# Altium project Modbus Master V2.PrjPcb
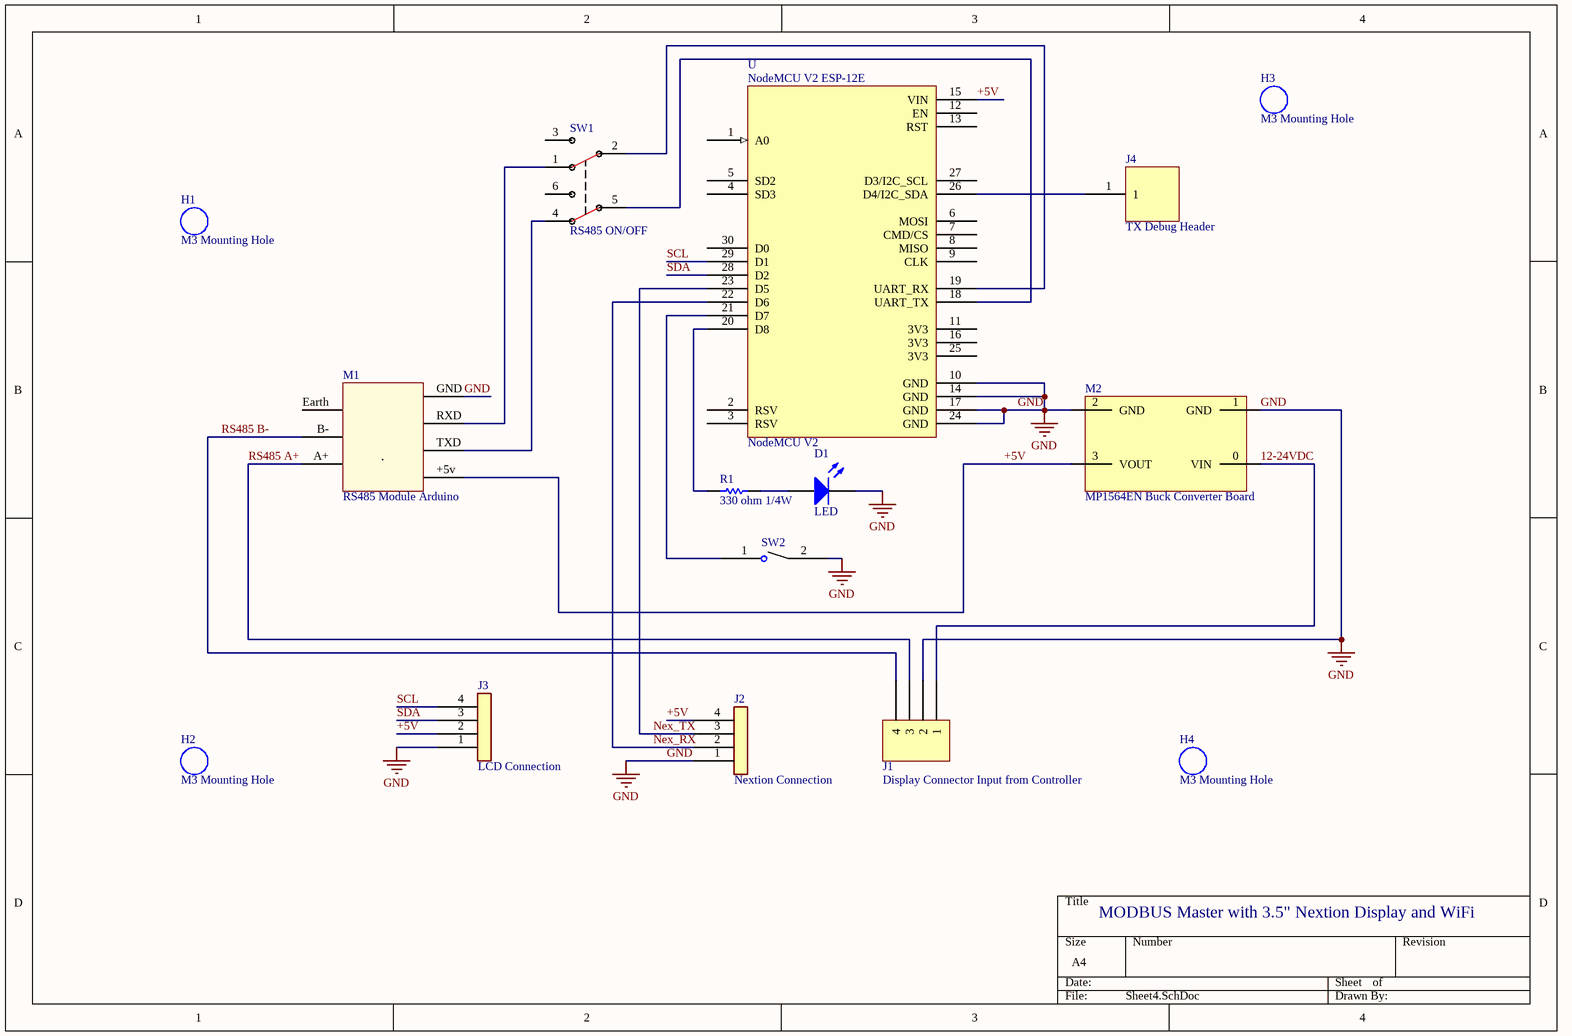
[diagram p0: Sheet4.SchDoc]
1 sheet, 15 parts. Net scope: global (net labels, ports and power ports of the same name join across sheets).

## Sheet Sheet4.SchDoc
size A4

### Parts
D1  LED  [PCB-6hmn14p3euwrtpae4j9f-1]
H1  M3 Mounting Hole  [PCB-sb9r54v1ukudlsmquqqd-1]
H2  M3 Mounting Hole  [PCB-sb9r54v1ukudlsmquqqd-1]
H3  M3 Mounting Hole  [PCB-sb9r54v1ukudlsmquqqd-1]
H4  M3 Mounting Hole  [PCB-sb9r54v1ukudlsmquqqd-1]
J1  Display Connector Input from Controller  [PCB-7alpfj4z7cactpb4urhw-1]
J2  Nextion Connection  [PCB-tykp9fg8zejphh3ras5e-1]
J3  LCD Connection  [PCB-tykp9fg8zejphh3ras5e-1]
J4  TX Debug Header  [PCB-jazjlqhe2dz3b1rp09od-1]
M1  RS485 Module Arduino  [PCB-fd05ettsbss648nlesx9-1]
M2  MP1564EN Buck Converter Board  [PCB-li055xbo9p6zs65dyiu8-1]
R1  330 ohm 1/4W  [PCB-b0svi7yxgb64se8nuirk-1]
SW1  RS485 ON/OFF  [PCB-4o0hqz6pdnge3ng8ta2d-1]
SW2  TE Connectivity 1825910-7  [PCB-6xsl2ocvzxedp18o12ji-1]  (value not drawn)
U  NodeMCU V2  [PCB-1qpvucnc8d0r5y38cwmb-1]

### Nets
GND: D1.2(K) J1.2 J2.1 J3.1 M1.GND M2.1(GND) M2.2(GND) SW2.2 U.10(GND) U.14(GND) U.17(GND) U.24(GND)
12-24VDC: J1.1 M2.0(VIN)
+5V: J2.4 J3.2 M1.+5v(+5V) M2.3(VOUT) U.15(VIN)
Nex_RX: J2.2 U.22(D6)
Nex_TX: J2.3 U.23(D5)
RS485 A+: J1.3 M1.A+
RS485 B-: J1.4 M1.B-
SCL: J3.4 U.29(D1)
SDA: J3.3 U.28(D2)
NetD1_1: D1.1(A) R1.1
NetJ4_1: J4.1 U.26(D4/I2C_SDA)
NetM1_RXD: M1.RXD SW1.1
NetM1_TXD: M1.TXD SW1.4
NetR1_2: R1.2 U.20(D8)
NetSW1_2: SW1.2 U.19(UART_RX)
NetSW1_5: SW1.5 U.18(UART_TX)
NetSW2_1: SW2.1 U.21(D7)

Not connected (* = marked no-connect by the designer): M1 Earth; SW1 3 6; U 1(A0) 2(RSV) 3(RSV) 4(SD3) 5(SD2) 6(MOSI) 7(CMD/CS) 8(MISO) 9(CLK) 11(3V3) 12(EN) 13(RST) 16(3V3) 25(3V3) 27(D3/I2C_SCL) 30(D0)

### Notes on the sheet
- MODBUS Master with 3.5" Nextion Display and WiFi

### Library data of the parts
D1 = CMP-9d1f5758637d42d8-1: TLHR5205 Red LED, 625 nm 5mm (T-1 3/4), Round Lens Through Hole package; Peak Wavelength: 635 nm; Wavelength: 625 nm; Lead-Free Status: Lead Free; Luminous Intensity: 70.0 mcd; Viewing Angle: 14 °; Lead Length: 24.0 mm; Voltage Rating (DC): 2.00 V
H1-H4 = CMP-2eajnev4pcr11g3c6yc7-1: M3 Mountig Hole
J1 = CMP-8a8e41e0d7ca5549-1: Header Shrouded 4 Position 5.08 mm Pitch Euro Style Terminal Block; Manufacturer Part Number: 796636-4; Number of Contacts: 4; Gender: Male; ELV Compliant: Compliant; Lead-Free Status: Lead Free
J2 J3 = CMP-pb4m6phizd15df6m9aeg-2: 4 pin right angle header
J4 = CMP-b1d07a80737d6e17-5: AMPMODU 1 Position 2.54 mm Single Row Through Hole Straight Header
M1 = CMP-3b2urf91aox2uunr70m7-5: RS485 Module with auto flow control
M2 = CMP-21c200n1kdmmc9b8929b-12: Popular low profile breakout board
R1 = CMP-b3d47a8ce28e6c13-3: Resistor; Metal Film; Res 1 Kilohms; Pwr-Rtg 0.25 W; Tol 0.1%; Axial; TCR 15 ppm/DegC; Manufacturer Part Number: YR1B1K0CC; Temperature Coefficient: -15.0 ppm/°C to 15.0 ppm/°C; Lead Length: 25.0 mm; Voltage Rating (DC): 500 V; ELV Compliant: Compliant
SW1 = CMP-0b36c2500016d4f1-7: JS Series DPDT On-On PC Pin Through Hole Subminiature Slide Switch; Lead-Free Status: Lead Free
SW2 = CMP-03bacadb7a6bdc7d-2: Switch Tactile OFF (ON) SPST Round Button PC Pins 0.05A 24VDC 100000Cycles 2.55N Thru-Hole Loose; Lead-Free Status: Lead Free; ELV Compliant: Compliant
U = CMP-e3f12eb858a53c36-4: NodeMCU V2 Featuring ESP-12E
